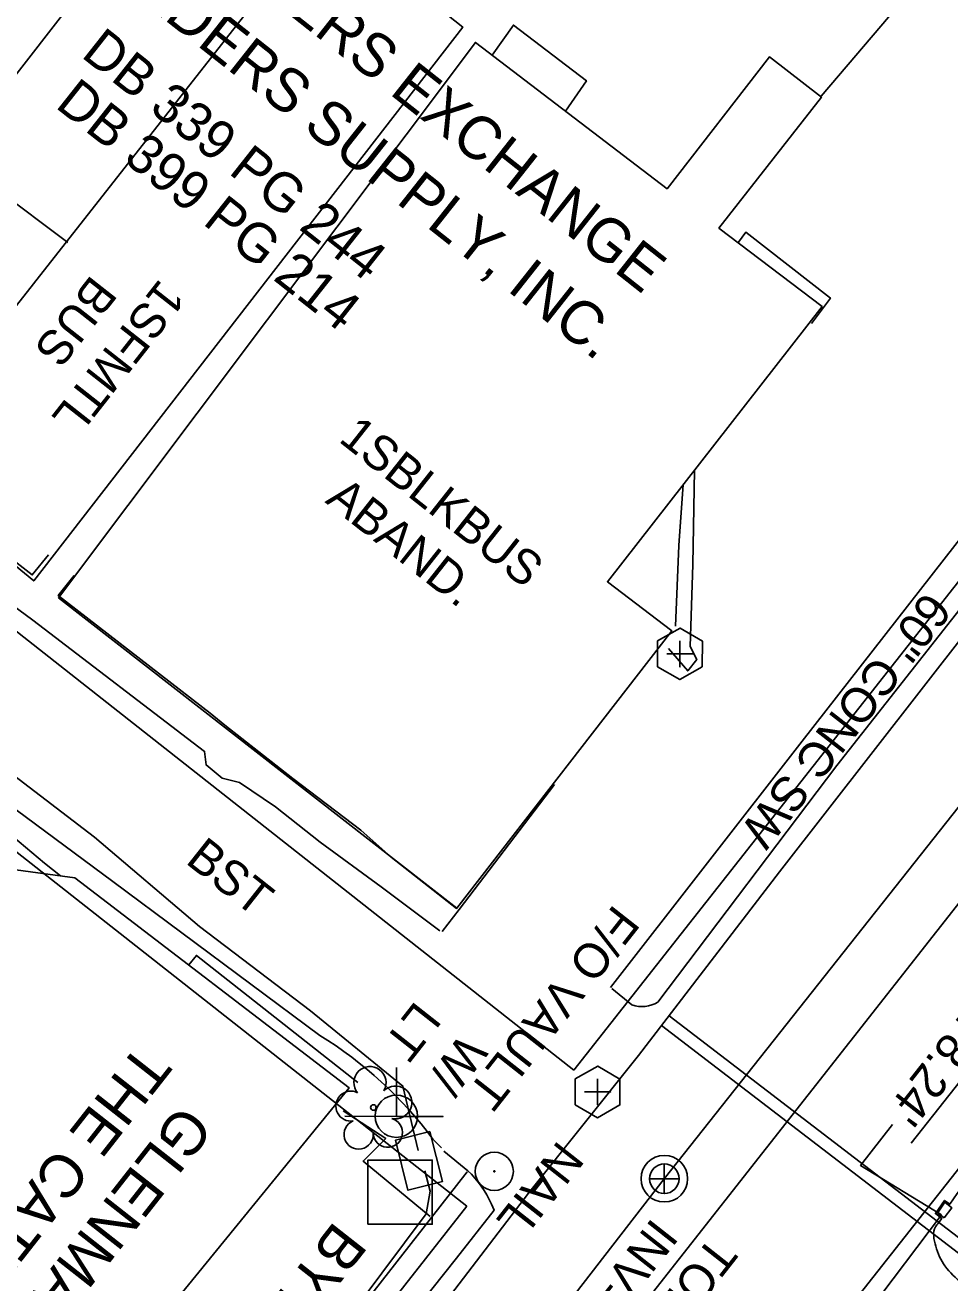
# Model space of a CAD drawing. Extents: x 553786 to 558838, y 502329 to 507342.
# Drawn here: x 558211.4 to 558318.3, y 506370.1 to 506515.5 of the extents above; entities that cross this region are included whole.
import ezdxf

# ---------------------------------------------------------------- set-up
doc = ezdxf.new("R2010")
doc.units = 0
for name, color, linetype in [('CTL Secondary Horizontal and Vertical Text', 7, 'Continuous'), ('Exist Building Text', 7, 'Continuous'), ('Exist Hydrographic Top of Bank', 7, 'Continuous'), ('Exist Property Deed Book Text', 7, 'Continuous'), ('Exist Property Iron Pin Text', 7, 'Continuous'), ('Exist Property Owner Text', 7, 'Continuous'), ('Exist Roads EOP Other Text', 7, 'Continuous'), ('Exist Roads EOP Text', 7, 'Continuous'), ('Exist Structure Minor Drop Inlet', 7, 'Continuous'), ('Exist Structure Minor Pipes CMP 18 Inch', 7, 'Continuous'), ('Exist Structure Minor Pipes CMP 18 Inch Invert', 7, 'Continuous'), ('Exist Structure Minor Pipes CMP 18 Inch Leader', 7, 'Continuous'), ('Exist Utilities Power Joint Use Telephone CELL', 7, 'Continuous'), ('Exist Utilities Power Pole Text', 7, 'Continuous'), ('Exist Utilities Sanitary Sewer Manhole Text', 7, 'Continuous'), ('Exist Utilities Sanitary Sewer UG Line', 7, 'Continuous'), ('Exist Utilities Sanitary Sewer UG Line Invert Elevation', 7, 'Continuous'), ('Exist Utilities Telephone Pedestal Text', 7, 'Continuous'), ('Exist Vegetation Tree CELL', 7, 'Continuous'), ('Prop Drainage Structure Catch Basin Grate 840 03F Label', 7, 'Continuous'), ('Prop Drainage Structure Headwall CELL', 7, 'Continuous'), ('Prop Drainage Structure Pipe Alternate 18in', 7, 'Continuous'), ('Prop Drainage Structure Pipe Alternate 24in', 7, 'Continuous'), ('Prop Drainage Structure Pipe Alternate 36in', 7, 'Continuous'), ('Prop Drainage Structure Pipe RCP 15in Class III Label', 7, 'Continuous'), ('Prop Drainage Structure Pipe RCP 15in Class IV', 7, 'Continuous'), ('Prop Drainage Structure Pipe RCP 30in Class III Label', 7, 'Continuous'), ('Prop Drainage Structure Pipe RCP 42in Class III Label', 7, 'Continuous'), ('Prop Drainage Structure Pipe Removal', 7, 'Continuous'), ('Prop Drainage Structure Plot Symbol 50 Scale', 7, 'Continuous'), ('Prop Earthen Structure Tail Ditch Label', 7, 'Continuous'), ('Prop Erosion Rip Rap Pad Outlet for Jurisdictional Stream CELL', 7, 'Continuous'), ('Sheet Layout Plan Border', 7, 'Continuous')]:
    doc.layers.add(name, color=color, linetype=linetype)

# ---------------------------------------------------------------- blocks, each defined once
blk = doc.blocks.new('CTL SECONDARY HORIZONTAL AND VERTICAL')
at = {"layer": 'Prop Drainage Structure Pipe Alternate 18in'}
blk.add_line((0, 0), (0, 0), dxfattribs=at)
blk.add_lwpolyline([(-0.1043, 0.0004), (0.0005, 0.1052), (0.1055, 0.0002), (0.0007, -0.1047)], close=True, dxfattribs=at)
blk = doc.blocks.new('EXIST UTILITIES SANITARY SEWER MANHOLE')
at = {"layer": 'Prop Drainage Structure Catch Basin Grate 840 03F Label'}
blk.add_lwpolyline([(0, 0.03425), (0, -0.03425), (0, 0), (0.03425, 0), (-0.03425, 0)], dxfattribs=at)
for radius in [0.05389, 0.03425]:
    blk.add_circle((0, 0), radius, dxfattribs=at)
blk = doc.blocks.new('EXIST UTILITIES SANITARY SEWER CLEAN-OUT')
at = {"layer": 'Prop Drainage Structure Pipe RCP 30in Class III Label'}
blk.add_line((0, 0), (0, 0), dxfattribs=at)
blk.add_lwpolyline([(-0.0516, 0.0299), (-0.0517, -0.0297), (-0.0001, -0.0596), (0.0516, -0.0299), (0.0517, 0.0297), (0.0001, 0.0596)], close=True, dxfattribs=at)
blk.add_lwpolyline([(0, 0.0302), (0, -0.0302), (0, 0), (0.0302, 0), (-0.0302, 0)], dxfattribs=at)
blk = doc.blocks.new('EXIST PROPERTY IRON PIN')
at = {"layer": 'Prop Drainage Structure Pipe RCP 15in Class IV'}
for radius in [0.0441, 0.00141]:
    blk.add_circle((0, 0), radius, dxfattribs=at)

msp = doc.modelspace()

# ---------------------------------------------------------------- linework, layer by layer
at = {"layer": 'Exist Hydrographic Top of Bank'}
for points in [[(557909.94, 506652.47), (557928.59, 506638.96), (557968.67, 506612.22), (558004.69, 506586.7), (558028.82, 506567.27), (558064.95, 506539.38), (558090.15, 506521.48), (558129.49, 506492.79), (558158.11, 506470.17), (558184.37, 506448.45), (558219.38, 506421.65), (558231.51, 506411.31), (558244.36, 506401.59), (558255.04, 506392.87), (558256.82, 506385.42)], [(558257.59, 506383.07), (558258.19, 506380.71), (558257.73, 506378.12), (558244.99, 506361.02), (558226.41, 506335.42), (558218.6, 506323.46), (558212.44, 506309.96), (558209.07, 506301.52), (558193.11, 506291.4), (558182.7, 506286.78), (558173.46, 506282.16), (558159.24, 506272.92)]]:
    msp.add_lwpolyline(points, dxfattribs=at)
at = {"layer": 'Exist Structure Minor Drop Inlet'}
msp.add_lwpolyline([(558317.62, 506377.64), (558316.84, 506378.2), (558317.71, 506379.44), (558318.51, 506378.82), (558317.62, 506377.64)], dxfattribs=at)
at = {"layer": 'Exist Structure Minor Pipes CMP 18 Inch'}
msp.add_line((558317.32, 506378.01), (558245.67, 506283.06), dxfattribs=at)
at = {"layer": 'Exist Structure Minor Pipes CMP 18 Inch Leader'}
msp.add_lwpolyline([(558317.32, 506378.01), (558307.96, 506383.7), (558311.66, 506388.42)], dxfattribs=at)
at = {"layer": 'Exist Utilities Power Joint Use Telephone CELL'}
msp.add_line((558254.29, 506389.39), (558254.29, 506389.39), dxfattribs=at)
msp.add_lwpolyline([(558248.35, 506389.39), (558259.69, 506389.35), (558254.29, 506389.37), (558254.29, 506395.01)], dxfattribs=at)
msp.add_circle((558254.29, 506389.39), 2.45, dxfattribs=at)
at = {"layer": 'Exist Utilities Sanitary Sewer UG Line'}
for p, q in [((558394.19, 506519.79), (558285.27, 506382.17)), ((558285.27, 506382.17), (558226.19, 506305.87))]:
    msp.add_line(p, q, dxfattribs=at)
at = {"layer": 'Exist Vegetation Tree CELL'}
msp.add_line((558251.63, 506390.4), (558251.63, 506390.4), dxfattribs=at)
msp.add_circle((558251.63, 506390.4), 0.326, dxfattribs=at)
for centre, radius, start, end in [((558251.24, 506393.27), 1.86, 330.1651, 219.7134), ((558254.18, 506390.99), 1.9, 257.1011, 134.1999), ((558249.02, 506390.56), 1.73, 62.6636, 279.3457), ((558249.92, 506387.28), 1.69, 111.5671, 6.231), ((558253.3, 506387.5), 1.7, 181.2822, 74.56)]:
    msp.add_arc(centre, radius, start, end, dxfattribs=at)
at = {"layer": 'Prop Drainage Structure Headwall CELL'}
msp.add_lwpolyline([(558393.2, 506486.82), (558375.25, 506464.1), (558353.15, 506436.08), (558331.55, 506408.69), (558313.81, 506386.28)], dxfattribs=at)
at = {"layer": 'Prop Drainage Structure Pipe Alternate 24in'}
for p, q in [((558284.95, 506399.88), (558322.24, 506371.27)), ((558285.82, 506401.01), (558323.19, 506372.35))]:
    msp.add_line(p, q, dxfattribs=at)
msp.add_lwpolyline([(558392.9, 506555.16), (558384.83, 506545.48), (558368.78, 506526.06), (558368.34, 506512.13), (558366.39, 506503.58), (558342.53, 506474.11), (558325.81, 506452.61), (558298.58, 506417.66), (558282.3, 506396.42), (558269.57, 506380.5), (558242, 506344.48), (558223.18, 506316.98), (558212.1, 506287.29), (558207.18, 506261.28)], dxfattribs=at)
at = {"layer": 'Prop Drainage Structure Pipe Alternate 36in'}
for p, q in [((558221.51, 506416.52), (558202.8, 506430.39)), ((558245.43, 506398.72), (558221.51, 506416.52)), ((558281.52, 506402.26), (558279.21, 506404.17)), ((558259.5, 506385.72), (558258.5, 506386.74)), ((558259.76, 506385.34), (558262.54, 506383.09))]:
    msp.add_line(p, q, dxfattribs=at)
for points in [[(558370.84, 506512.75), (558349.42, 506486.21), (558327.04, 506457.64), (558305.21, 506429.92), (558284.53, 506402.58)], [(558402.48, 506486.14), (558398.64, 506481.32), (558397.59, 506481.99), (558396.08, 506480), (558396.99, 506479.22), (558381.74, 506459.58), (558359.41, 506431.29), (558337.74, 506403.64), (558319.13, 506380.46), (558318.27, 506379.22), (558317.68, 506379.66), (558316.61, 506378.14), (558317.36, 506377.56), (558316.98, 506377.08)], [(558259.33, 506410.84), (558252.55, 506415.91), (558245.48, 506421.08), (558240.32, 506425.14), (558236.14, 506427.97), (558234.14, 506428.47), (558232.29, 506430), (558232.12, 506431.57), (558212.27, 506446.74), (558203.26, 506453.38), (558193, 506461.97), (558193.44, 506462.7), (558194.35, 506462.73), (558196.07, 506463.73), (558195.67, 506464.37), (558197.03, 506465.92), (558206.28, 506477.79)], [(558272.58, 506427.72), (558261.56, 506413.28), (558259.58, 506410.75)], [(558258.19, 506377.79), (558250.44, 506384.21), (558253.07, 506386.8), (558248.14, 506390.02)], [(558265.29, 506379.24), (558265.58, 506378.54), (558261.26, 506372.99), (558248.8, 506357.33)]]:
    msp.add_lwpolyline(points, dxfattribs=at)
for centre, major_axis, ratio, start_param, end_param in [((558282.72, 506405.59), (3.33, 1.29), 0.984082, 4.005477, 4.880373), ((558220.77, 506358.99), (46.38, 6.91), 0.99552, 0.487973, 0.869621), ((558253.85, 506373.97), (6.05, 11.06), 0.999149, 5.643916, 6.022268)]:
    msp.add_ellipse(centre, major_axis=major_axis, ratio=ratio, start_param=start_param, end_param=end_param, dxfattribs=at)
msp.add_spline([(558316.98, 506377.08), (558316.62, 506376.61), (558316.65, 506374.36), (558317.71, 506372.09), (558322.29, 506368.45)], degree=3, dxfattribs=at)
at = {"layer": 'Prop Drainage Structure Pipe RCP 15in Class III Label'}
for p, q in [((558370.6, 506516.46), (558274.8, 506394.7)), ((558404.32, 506491.4), (558307.81, 506368.73)), ((558139.83, 506475.44), (558262.43, 506378.98)), ((558206.98, 506448.05), (558274.8, 506394.7)), ((558262.43, 506378.98), (558197.82, 506296.85))]:
    msp.add_line(p, q, dxfattribs=at)
at = {"layer": 'Prop Drainage Structure Pipe RCP 42in Class III Label'}
for points in [[(558285.76, 506443.45), (558287.98, 506440.86), (558289.01, 506442.17), (558288.25, 506443.68), (558288.55, 506453.18), (558288.76, 506464.09)], [(558286.55, 506446.05), (558286.96, 506455.38), (558287.45, 506462.41)]]:
    msp.add_lwpolyline(points, dxfattribs=at)
at = {"layer": 'Prop Drainage Structure Pipe Removal'}
msp.add_lwpolyline([(558258.16, 506387.62), (558259.62, 506381.83), (558255.62, 506380.83), (558254.17, 506386.62)], close=True, dxfattribs=at)
at = {"layer": 'Prop Drainage Structure Plot Symbol 50 Scale'}
msp.add_line((558216.3, 506490.41), (558202.98, 506500.38), dxfattribs=at)
for points in [[(558311.69, 506532.08), (558319.2, 506525.87), (558303.39, 506507.31)], [(558364.41, 506518.52), (558343.46, 506491.31), (558325.28, 506467.76), (558327.3, 506466.06), (558323.09, 506460.81), (558301.19, 506432.75), (558279.05, 506404.27)], [(558214.06, 506454.29), (558212.19, 506451.97), (558197.77, 506463.16), (558196.14, 506464.48)], [(558261.24, 506413.42), (558253.7, 506419.35), (558250.18, 506422.46), (558242.31, 506428.45), (558234.45, 506434.59), (558232.76, 506435.99), (558215.2, 506449.57), (558217.05, 506451.88)], [(558262.48, 506382.96), (558258.35, 506377.7), (558245.08, 506360.71), (558234.9, 506347.67), (558233.01, 506349.19), (558227.28, 506354), (558224.62, 506356.22)]]:
    msp.add_lwpolyline(points, dxfattribs=at)
at = {"layer": 'Prop Earthen Structure Tail Ditch Label'}
for points in [[(558293.85, 506490.43), (558294.68, 506491.57), (558304.47, 506483.97), (558302.29, 506481.02)], [(558215.47, 506417.18), (558213.62, 506418.65), (558207.71, 506423.56), (558204.82, 506424.83), (558202.59, 506425.36), (558200.55, 506425.27), (558190.92, 506423.1)]]:
    msp.add_lwpolyline(points, dxfattribs=at)
at = {"layer": 'Prop Erosion Rip Rap Pad Outlet for Jurisdictional Stream CELL'}
for points in [[(558164.49, 506526.25), (558237.89, 506620.54), (558273.7, 506591.36), (558200.87, 506497.67)], [(558195.92, 506464.77), (558245.52, 506527.88), (558250.8, 506524.01), (558253.34, 506527.15), (558261.42, 506520.82), (558259.01, 506517.64), (558261.97, 506515.29), (558212.37, 506451.28)], [(558215.22, 506449.3), (558263.43, 506513.53), (558285.59, 506496.61), (558297.44, 506511.87), (558303.44, 506507.19), (558291.58, 506492.06), (558303.5, 506482.99), (558278.69, 506451.18), (558286.12, 506445.52), (558261.29, 506413.43)]]:
    msp.add_lwpolyline(points, close=True, dxfattribs=at)
for points in [[(558265.37, 506512.06), (558267.82, 506515.52), (558276.27, 506509.09), (558273.86, 506505.57)], [(558142.32, 506341.17), (558074.94, 506393.32), (558074.51, 506396.69), (558134.91, 506476.38), (558136.16, 506475.38), (558139.05, 506479.14), (558153.28, 506467.58), (558130.8, 506437.69), (558134.02, 506435.21), (558131.59, 506431.63), (558132.85, 506430.79), (558129.99, 506426.75), (558128.52, 506427.79), (558123.02, 506420.67), (558124.35, 506419.74), (558109.54, 506400.22), (558162.01, 506359.31), (558209.7, 506417.97), (558217.11, 506416.96), (558248.83, 506392.69), (558200.38, 506333.33)], [(558230.28, 506406.89), (558231.17, 506407.98), (558249.82, 506393.29)]]:
    msp.add_lwpolyline(points, dxfattribs=at)
at = {"layer": 'Sheet Layout Plan Border'}
msp.add_line((558549.5, 506706.87), (558252.67, 506329.25), dxfattribs=at)

# ---------------------------------------------------------------- block references
at = {"layer": 'Prop Drainage Structure Catch Basin Grate 840 03F Label', "xscale": 50, "yscale": 50}
msp.add_blockref('EXIST UTILITIES SANITARY SEWER MANHOLE', (558285.27, 506382.17), dxfattribs=at)
at = {"layer": 'Prop Drainage Structure Pipe Alternate 18in', "xscale": 50, "yscale": 49.99999999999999, "rotation": 44.99999999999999}
msp.add_blockref('CTL SECONDARY HORIZONTAL AND VERTICAL', (558254.71, 506380.58), dxfattribs=at)
at = {"layer": 'Prop Drainage Structure Pipe RCP 15in Class IV', "xscale": 50, "yscale": 50}
msp.add_blockref('EXIST PROPERTY IRON PIN', (558265.61, 506383.02), dxfattribs=at)
at = {"layer": 'Prop Drainage Structure Pipe RCP 30in Class III Label', "xscale": 50, "yscale": 50}
for p in [(558287.08, 506442.84), (558277.56, 506392.2)]:
    msp.add_blockref('EXIST UTILITIES SANITARY SEWER CLEAN-OUT', p, dxfattribs=at)

# ---------------------------------------------------------------- texts
at = {"layer": 'CTL Secondary Horizontal and Vertical Text'}
msp.add_text('BY7-20', height=5, rotation=231.8306, dxfattribs=at).set_placement((558247.19, 506377.42))
at = {"layer": 'Exist Building Text'}
for s, rotation, p in [('BUS', 231.8306, (558219.06, 506486.79)), ('1SFMTL', 231.8306, (558226.98, 506486.34)), ('1SBLKBUS', 321.6667, (558247.49, 506467.47)), ('ABAND.', 321.6667, (558245.95, 506460.4))]:
    msp.add_text(s, height=4, rotation=rotation, dxfattribs=at).set_placement(p)
at = {"layer": 'Exist Property Deed Book Text'}
for s, p in [('DB 339 PG 244', (558217.71, 506511.93)), ('DB 399 PG 214', (558214.72, 506506.09))]:
    msp.add_text(s, height=4.5, rotation=321.6667, dxfattribs=at).set_placement(p)
at = {"layer": 'Exist Property Iron Pin Text'}
msp.add_text('NAIL', height=4, rotation=231.8306, dxfattribs=at).set_placement((558273.05, 506386.73))
at = {"layer": 'Exist Property Owner Text'}
for s, rotation, p in [('CLAY FARMERS EXCHANGE', 321.6667, (558211.11, 506541.05)), ('AND BUILDERS SUPPLY, INC.', 321.6667, (558203.13, 506535.38)), ('THE CATHOLIC CHURCH', 231.8306, (558224.58, 506398.01)), ('GLENMARY ORDER OF', 231.8306, (558229.38, 506390.98))]:
    msp.add_text(s, height=5, rotation=rotation, dxfattribs=at).set_placement(p)
at = {"layer": 'Exist Roads EOP Other Text'}
msp.add_text('60" CONC SW', height=4, rotation=232.03, dxfattribs=at).set_placement((558315.56, 506450.23))
at = {"layer": 'Exist Roads EOP Text'}
msp.add_text('BST', height=4, rotation=321.6667, dxfattribs=at).set_placement((558229.78, 506418.73))
at = {"layer": 'Exist Structure Minor Pipes CMP 18 Inch Invert'}
msp.add_text("INV=1878.24'", height=4, rotation=231.8306, dxfattribs=at).set_placement((558330.97, 506415.81))
at = {"layer": 'Exist Utilities Power Pole Text'}
for s, p in [('LT', (558256.53, 506402.86)), ('W/', (558261.86, 506399.12))]:
    msp.add_text(s, height=4, rotation=231.8306, dxfattribs=at).set_placement(p)
at = {"layer": 'Exist Utilities Sanitary Sewer Manhole Text'}
msp.add_text("TOP=1880.56'", height=4, rotation=231.8306, dxfattribs=at).set_placement((558290.76, 506375.72))
at = {"layer": 'Exist Utilities Sanitary Sewer UG Line Invert Elevation'}
msp.add_text("INV=1876.36'", height=4, rotation=231.8306, dxfattribs=at).set_placement((558283.93, 506377.78))
at = {"layer": 'Exist Utilities Telephone Pedestal Text'}
msp.add_text('F/O VAULT', height=4, rotation=231.8306, dxfattribs=at).set_placement((558279.49, 506414.02))

doc.saveas('drawing.dxf')
